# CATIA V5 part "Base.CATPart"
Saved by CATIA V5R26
Part number: Part1
Bounding box of the stored display mesh (mm): x -50 to 50, y -25 to 25, z 0 to 50
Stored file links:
  D:\_Deepak\CATIA\CATIA V5-6R2016_Deepak\Resources\Part files\Partfiles\c12_catia_v5_6r2016_prt\c12_catia_v5-6r2016 figr_12-15\Base.CATPart
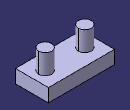
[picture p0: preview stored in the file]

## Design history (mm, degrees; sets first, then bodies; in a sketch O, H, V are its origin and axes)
Body1 (main body)
  Sketch1 on xy-plane, origin (0, 0, 0), H (1, 0, 0), V (0, 1, 0)
    line L1 (50, 25) -> (50, -25)
    line L2 (50, -25) -> (-50, -25)
    line L3 (-50, -25) -> (-50, 25)
    line L4 (-50, 25) -> (50, 25)
    circle A1 centre (-30, 0) radius 10
    point P5 (-30, 0)
    circle A2 centre (30, 0) radius 10
    length L2 = 100
    length L1 = 50
    radius A1 = 10
    distance P5 V = 30
    vertical: L1 V, L3 V
    horizontal: L2 H, L4 H
    equidistance: L1 L3 O, L2 L4 O
    coincidence: P5 H
    symmetry: A1 A2 V
  MultiPad1: profile Sketch1, domains (length 20; length 50; length 50)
